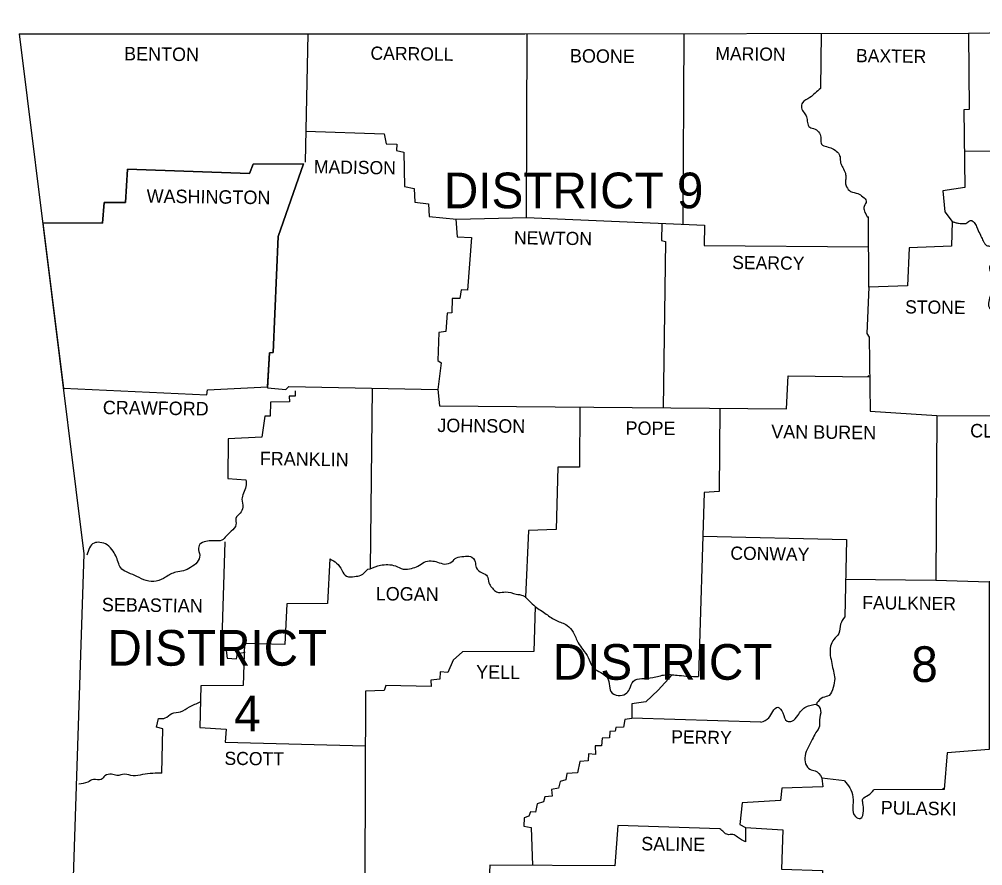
# Model space of a CAD drawing. Extents: x 31699 to 244310, y -8841 to 11474.
# Drawn here: x 77768 to 80783, y 7711 to 10358 of the extents above; entities that cross this region are included whole.
import ezdxf

# ---------------------------------------------------------------- set-up
doc = ezdxf.new("R2010")
doc.units = 0
for name, color, linetype in [('Level 48', 7, 'Continuous'), ('Level 60', 7, 'Continuous'), ('R_Border', 7, 'Continuous'), ('R_Border Prem', 7, 'Continuous'), ('R_Grid', 7, 'Continuous')]:
    doc.layers.add(name, color=color, linetype=linetype)

msp = doc.modelspace()

# ---------------------------------------------------------------- linework, layer by layer
at = {"layer": 'Level 48'}
for p, q in [((80421.5, 9740.6), (80425.4, 9740.6)), ((80263.9, 8220.2), (80263, 8215.3)), ((80279.6, 7986.3), (80279.6, 7984.4))]:
    msp.add_line(p, q, dxfattribs=at)
at = {"layer": 'Level 60'}
for p, q in [((77841.7, 9721.1), (77906.1, 9204.6)), ((78545, 9208.5), (78550.7, 9315))]:
    msp.add_line(p, q, dxfattribs=at)
for points in [[(78550.7, 9315), (78562.5, 9316), (78578.1, 9679), (78657.4, 9906), (78499.9, 9905), (78488.1, 9875.6), (78106.5, 9889.3), (78100.7, 9784.6), (78033.2, 9784.6), (78028.3, 9720.1), (77841.7, 9721.1)], [(77906.1, 9204.6), (78355.1, 9183.9), (78357, 9199.6), (78545, 9208.5)]]:
    msp.add_lwpolyline(points, dxfattribs=at)
at = {"layer": 'R_Border Prem'}
for p, q in [((78858.9, 8638.9), (78865.8, 8639.9)), ((79351.7, 8551.2), (79351.7, 8548.9)), ((78334.5, 8223.1), (78335, 8223.3))]:
    msp.add_line(p, q, dxfattribs=at)
for points in [[(77768, 10313), (79350.1, 10312), (80738.5, 10314.9), (82376.3, 10340.4), (83135.6, 10358)], [(77768, 10313), (77970.5, 8686.9), (77882.5, 6032.5)], [(78671.2, 10312.4), (78662.3, 9910.9)], [(78664.4, 10007.9), (78909.8, 9999.9), (78915.7, 9968.6), (78949, 9967.6), (78948, 9948), (78971.5, 9942.2), (78973.4, 9835.5), (79003.7, 9828.7), (79005.7, 9786.6), (79048.8, 9780.7), (79050.7, 9741.6), (79135.8, 9732.8), (79355, 9737.7), (79357, 10312)], [(79847.2, 10313.1), (79844.2, 9717.1)], [(80277.7, 10314), (80275.7, 10141.8)], [(80738.4, 10314.9), (80740.4, 10076.2), (80723.8, 10075.2), (80726.7, 9831.6), (80658.2, 9821.8), (80664.1, 9756.3), (80687.6, 9725.9), (80685.6, 9648.7), (80552.6, 9643.8), (80547.7, 9524.4), (80426.3, 9520.5), (80420.5, 9375.7), (80427.3, 9363.9), (80430.3, 9133), (80639.6, 9119.3), (80636.7, 8603.7), (80803, 8598.8), (80803, 8074.4), (80671.9, 8064.6), (80662.1, 7949.2), (80442, 7948.2)], [(81567.1, 10327.8), (81569.1, 10081.1), (81441.9, 10074.3), (81438, 9941.2), (80725.4, 9945.1)], [(77841.7, 9721.1), (78028.3, 9720.1), (78033.2, 9784.6), (78100.7, 9784.6), (78106.5, 9889.3), (78488.1, 9875.6), (78499.9, 9905), (78657.4, 9906), (78578.1, 9679), (78562.5, 9316), (78550.7, 9315), (78544.9, 9205.4), (78602.6, 9200.5), (78611.4, 9209.3), (79078.1, 9200.5), (79083, 9148.7)], [(80426.3, 9520.5), (80425.4, 9740.6)], [(79133.7, 9733), (79137.8, 9678), (79182.8, 9675.1), (79171.1, 9510.7), (79150.5, 9511.7), (79146.6, 9485.3), (79123.1, 9485.3), (79122.1, 9440.2), (79107.5, 9439.3), (79102.6, 9381.5), (79081, 9378.6), (79078.1, 9290.6), (79087.9, 9283.7), (79078.1, 9200.5)], [(79355, 9737.7), (79912.7, 9714.2), (79911.7, 9650.6), (80425.8, 9646.7)], [(79778.7, 9719.8), (79777.7, 9666.3), (79790.4, 9663.3), (79782.5, 9143)], [(79083, 9148.7), (80169, 9139.9), (80173.9, 9242.6), (80428.9, 9239.6)], [(80423.4, 9240.7), (80426.3, 9243.6)], [(77906.1, 9204.6), (78355.1, 9183.9), (78357, 9199.6), (78545, 9208.5)], [(78631, 9196.6), (78631, 9179), (78612.4, 9179), (78613.4, 9161.4), (78553.7, 9160.4), (78552.7, 9116.4), (78536.1, 9116.4), (78527.3, 9050.8), (78421.6, 9046), (78420.6, 8921.7), (78477.4, 8917.8)], [(78872.6, 9204.5), (78865.8, 8639.9)], [(79522.3, 9145.1), (79521.3, 8957.9), (79453.8, 8956.9), (79447.9, 8762.2), (79361.8, 8759.3), (79351.7, 8551.2)], [(79960.7, 9141.6), (79958.7, 8881.6), (79911.7, 8877.7), (79893.1, 8302.4)], [(80639.6, 9119.3), (81142.5, 9116.4), (81185.6, 9136.9), (81182.7, 8754.4), (81153.3, 8741.7), (81126.9, 8719.2), (81118.1, 8710.4), (81117.1, 8600.8), (80803, 8598.8)], [(78410.8, 8724.1), (78401, 8387.5), (78415.7, 8383.6), (78418.7, 8360.1), (78448, 8358.1), (78450.9, 8374.8), (78474.4, 8378.7)], [(79907.3, 8741.7), (80356.9, 8730.9), (80351, 8489.2)], [(78739.6, 8671.2), (78732.7, 8531.3), (78605.5, 8530.3), (78598.7, 8403.1), (78472.5, 8406.1), (78468.6, 8275), (78336.5, 8274), (78332.6, 8142.9), (78415.7, 8138), (78412.8, 8097.9), (78850.5, 8085.8)], [(80352, 8607.6), (80636.7, 8603.7)], [(79382.4, 8521.5), (79378.5, 8380.6), (79155.4, 8379.7), (79126, 8354.2), (79109.4, 8315.1), (79085, 8317), (79084, 8294.5), (79055.6, 8291.6), (79056.6, 8271.1), (78914.7, 8275), (78909.8, 8259.3), (78851.1, 8257.4), (78849.2, 7685)], [(79810.5, 8307.5), (79766.9, 8260.3), (79728.7, 8224.1), (79684.7, 8217.2), (79684.7, 8171.3), (79663.2, 8168.3), (79659.3, 8144.8), (79634.8, 8142.9), (79632.9, 8132.1), (79616.2, 8131.1), (79615.3, 8110.6), (79591.8, 8109.6), (79589.8, 8086.1), (79570.2, 8086.1), (79571.2, 8058.7), (79549.7, 8060.7), (79548.7, 8039.2), (79522.3, 8037.2), (79514.5, 8002), (79481.2, 7999.1), (79478.3, 7979.5), (79460.7, 7974.6), (79455.8, 7954), (79433.3, 7949.2), (79435.2, 7928.6), (79412.7, 7926.7), (79408.8, 7911), (79388.3, 7905.1), (79383.4, 7878.7), (79367.7, 7879.7), (79362.8, 7866), (79348.1, 7861.1), (79347.2, 7834.7), (79369.7, 7830.8), (79373.8, 7711.7)], [(78214.2, 8001), (78217.1, 8139), (78197.5, 8144.8), (78203.4, 8171.3)], [(80088.8, 8159.5), (79684.7, 8172.3)], [(80350, 7976.6), (80279.6, 7984.4), (80282.5, 7958), (80154.4, 7953.1), (80150.4, 7914.9), (80030.1, 7908.1), (80023.2, 7839.6), (80040.9, 7830.8), (80040.9, 7785.8)], [(80657.3, 7950.1), (80662.1, 7955)], [(79960.6, 7826.9), (79640.7, 7836.6), (79631.9, 7710.4), (79240.5, 7712.4), (79238.6, 7670.3)], [(80040.9, 7830.2), (80157.3, 7822.9), (80153.4, 7700.6), (80281.5, 7695.8), (80283.5, 7589.1), (80344.2, 7584.2), (80344.2, 7565.6), (80400.9, 7561.7), (80402.9, 7493.2), (80532, 7493.2), (80535.9, 7425.7), (80655.3, 7419.8), (80654.3, 7292.5)]]:
    msp.add_lwpolyline(points, dxfattribs=at)
for points in [[(80275.7, 10141.8), (80258.1, 10127.1), (80242.4, 10113.4), (80218.9, 10096.8), (80216, 10081.1), (80223.8, 10065.5), (80231.6, 10052.7), (80234.6, 10035.1), (80241.4, 10020.4), (80258.1, 10014.6), (80271.8, 10001.9), (80276.7, 9984.2), (80278.6, 9967.6), (80294.3, 9959.8), (80311.9, 9953.9), (80328.5, 9942.2), (80336.3, 9927.5), (80338.3, 9908.9), (80345.1, 9894.2), (80353, 9876.6), (80354.9, 9861.9), (80353, 9847.3), (80356.9, 9833.6), (80369.6, 9819.9), (80392.1, 9813), (80407.8, 9803.2), (80418.5, 9789.5), (80411.7, 9772.9), (80412.7, 9758.2), (80421.5, 9740.6)], [(80687.6, 9725.9), (80697.2, 9722.3), (80707, 9720.3), (80716.9, 9719.5), (80726.7, 9719.1), (80732.8, 9721.1), (80738.9, 9725.5), (80744.7, 9728.9), (80747.5, 9729.2), (80750.2, 9727.9), (80755.8, 9722.3), (80760.1, 9716), (80763.6, 9709.3), (80766.8, 9702.5), (80775.6, 9682.9), (80782.4, 9668.5), (80786.1, 9661.4), (80788.2, 9657.9), (80790.3, 9654.5), (80794.9, 9650.8), (80801.1, 9649.2), (80807.7, 9648), (80810.9, 9647.1), (80813.8, 9645.7), (80831.4, 9630.1), (80833.9, 9621.6), (80833.3, 9617.2), (80831.4, 9613.4), (80827.7, 9609.4), (80823.7, 9605.6), (80819.6, 9601.8), (80815.8, 9597.8), (80814, 9595.9), (80808.4, 9590.4), (80805.4, 9586.5), (80804.5, 9584.4), (80804, 9582.1), (80804.3, 9577.5), (80805.4, 9572.9), (80806.8, 9568.2), (80807.9, 9563.5), (80810, 9550.8), (80811.8, 9538.1), (80811.8, 9513.6), (80806, 9491.1), (80801.1, 9470.6), (80800.6, 9466.1), (80801.2, 9461.7), (80803, 9457.3), (80804.3, 9455.1), (80806, 9453), (80808, 9451.3), (80810.2, 9450.5), (80815.1, 9451.2), (80824.6, 9455.9), (80829.5, 9459.4), (80834.1, 9463.6), (80838.9, 9467.7), (80844.1, 9470.6), (80849.1, 9471.8), (80854.4, 9472.3), (80864.7, 9470.6), (80874.7, 9465.7), (80884.2, 9459.8), (80889.5, 9454.9), (80894.1, 9449), (80899, 9443.8), (80901.7, 9442.1), (80903.2, 9441.5), (80904.8, 9441.2), (80915, 9442.2), (80925.3, 9445.1), (80942, 9450), (80965.5, 9456.9), (80982.1, 9448.1), (80996.8, 9436.3), (81001.3, 9431.8), (81005.5, 9427), (81009.8, 9422.2), (81014.4, 9417.7), (81031, 9406), (81052.5, 9395.2), (81059, 9393.1), (81065.6, 9391.7), (81072.3, 9390.3), (81078.9, 9388.4), (81092.8, 9382.4), (81098.7, 9377.9), (81101.3, 9375.1), (81102.4, 9373.5), (81103.4, 9371.8), (81105, 9368.2), (81107.3, 9357.6), (81107.5, 9350.5), (81107.3, 9343.4), (81106.3, 9318.9), (81104.4, 9288.6), (81102.4, 9255.3), (81102, 9247.2), (81102.1, 9239.1), (81103, 9231), (81104, 9227), (81105.4, 9223), (81110.5, 9212), (81116.1, 9201.5), (81123.1, 9189), (81129.8, 9176.1), (81132.9, 9164.5), (81133.4, 9158.6), (81133.7, 9152.6), (81134.2, 9134.5), (81132.9, 9116.5)], [(78477.4, 8917.8), (78477.4, 8897.2), (78469.5, 8875.7), (78464.6, 8857.1), (78467.6, 8832.7), (78458.8, 8813.1), (78446.1, 8797.4), (78446.1, 8777.9), (78431.4, 8757.3), (78415.7, 8741.7), (78402, 8728.9), (78377.6, 8727), (78357, 8726), (78336.5, 8719.2), (78328.6, 8704.5), (78332.6, 8682), (78324.7, 8660.5), (78304.2, 8643.8), (78281.7, 8633.1), (78258.2, 8629.2), (78225.9, 8613.5), (78196.6, 8600.8), (78165.3, 8602.7), (78135.9, 8615.5), (78109.5, 8627.2), (78088.9, 8638.9), (78072.3, 8675.1), (78061.5, 8694.7), (78043, 8714.3), (78020.4, 8722.1), (78001.9, 8720.1), (77979.4, 8682)], [(78739.6, 8671.2), (78761.1, 8657.5), (78777.7, 8635), (78792.4, 8616.4), (78816.9, 8615.5), (78836.4, 8619.4), (78858.9, 8638.9)], [(78865.8, 8639.9), (78898.1, 8650.7), (78921.6, 8652.6), (78945, 8648.7), (78969.5, 8638.9), (78995.9, 8640.9), (79015.5, 8647.7), (79035.1, 8660.5), (79056.6, 8664.4), (79077.1, 8660.5), (79098.7, 8654.6), (79122.1, 8661.4), (79135.8, 8674.2), (79159.3, 8678.1), (79179.9, 8678.1), (79194.5, 8661.4), (79197.5, 8643.8), (79216.1, 8627.2), (79232.7, 8616.4), (79237.6, 8595.9), (79246.4, 8581.2), (79255.2, 8571.4), (79267.9, 8565.6), (79289.4, 8567.5), (79322.7, 8560.7), (79344.2, 8555.8), (79363.8, 8539.1), (79382.4, 8521.5)], [(79382.4, 8521.5), (79416.6, 8498), (79448.9, 8477.5), (79482.2, 8462.8), (79500.8, 8441.3), (79517.4, 8408), (79531.1, 8387.5), (79548.7, 8362), (79561.4, 8333.7), (79582, 8318), (79603.5, 8304.3), (79614.3, 8279.9), (79619.2, 8255.4), (79642.6, 8243.7), (79665.1, 8248.5), (79677.9, 8263.2), (79689.6, 8288.7), (79716, 8296.5), (79750.3, 8299.4), (79789.4, 8308.2), (79832.5, 8306.3), (79893.1, 8302.4)], [(80351, 8489.2), (80338.3, 8466.7), (80332.4, 8437.4), (80316.8, 8418.8), (80307, 8397.3), (80306, 8368.9), (80310.9, 8343.5), (80315.8, 8319), (80319.7, 8296.5), (80314.8, 8268.1), (80302.1, 8243.7), (80282.5, 8236.8), (80263.9, 8220.2)], [(78203.4, 8171.3), (78224.9, 8173.2), (78245.5, 8186.9), (78272.9, 8192.8), (78300.3, 8207.5), (78334.5, 8223.1)], [(80088.8, 8159.5), (80113.3, 8173.2), (80126, 8193.8), (80141.6, 8206.5), (80157.3, 8188.9), (80171, 8163.4), (80185.7, 8163.4), (80204.3, 8181), (80216, 8196.7), (80230.7, 8208.4), (80246.3, 8213.3), (80263, 8215.3), (80275.7, 8196.7), (80271.8, 8167.3), (80271.8, 8147.8), (80261, 8127.2), (80249.3, 8105.7), (80236.5, 8081.2), (80226.8, 8054.8), (80228.7, 8029.4), (80242.4, 8012.8), (80258.1, 8007.9), (80279.6, 7986.3)], [(78214.2, 8001), (78185.8, 8000), (78153.5, 7996.1), (78124.2, 7992.2), (78097.7, 7997.1), (78073.3, 7993.2), (78056.6, 7997.1), (78036.1, 7992.2), (78024.4, 7980.5), (77999.9, 7980.5), (77982.3, 7972.6), (77953.9, 7965.8)], [(80350, 7976.6), (80366.7, 7955), (80376.5, 7925.7), (80376.5, 7892.4), (80384.3, 7865), (80399.9, 7859.1), (80409.7, 7882.6), (80407.8, 7906.1), (80407.8, 7919.8), (80424.4, 7931.5), (80442, 7948.2)], [(80040.9, 7785.8), (80015.4, 7800.4), (80000.7, 7809.2), (79985.1, 7808.3), (79972.4, 7816.1), (79960.6, 7826.9)]]:
    msp.add_spline(points, degree=3, dxfattribs=at)

# ---------------------------------------------------------------- texts
at = {"layer": 'R_Border'}
for s, height, rotation, p in [('BENTON', 42.07, 359.2527, (78095.8, 10229.8)), ('CARROLL', 41.09, 359.1481, (78866.8, 10231.8)), ('BOONE', 42.07, 359.4001, (79491, 10223)), ('MARION', 41.09, 359.1854, (79946, 10230.8)), ('BAXTER', 41.09, 359.2559, (80386.2, 10224)), ('MADISON', 41.09, 359.0906, (78689.7, 9876.6)), ('WASHINGTON', 42.06, 359.232, (78166.2, 9784.6)), ('NEWTON', 41.09, 359.2717, (79315.9, 9654.5)), ('SEARCY', 41.08, 359.2527, (79998.8, 9577.2)), ('STONE', 41.08, 359.4001, (80539.8, 9438.3)), ('CRAWFORD', 42.06, 359.2771, (78029.3, 9123.2)), ('JOHNSON', 42.07, 359.3514, (79076.1, 9067.5)), ('POPE', 42.07, 359.6155, (79665.1, 9058.7)), ('VAN BUREN', 42.07, 359.3508, (80121.1, 9047.9)), ('CLEBURNE', 42.06, 359.2535, (80743.4, 9050.8)), ('FRANKLIN', 42.07, 359.1815, (78520.4, 8963.8)), ('CONWAY', 41.08, 359.0371, (79992.9, 8668.3)), ('LOGAN', 42.07, 359.3969, (78883.4, 8541.1)), ('SEBASTIAN', 42.06, 359.2816, (78026.3, 8506.8)), ('FAULKNER', 41.09, 359.2486, (80405.8, 8513.7)), ('YELL', 42.07, 359.1987, (79197.5, 8296.5)), ('PERRY', 41.09, 359.0858, (79808, 8094)), ('SCOTT', 41.09, 359.4063, (78409.9, 8026.5)), ('PULASKI', 42.07, 359.053, (80463.5, 7871.9)), ('SALINE', 42.07, 359.1491, (79714.1, 7759.3))]:
    msp.add_text(s, height=height, rotation=rotation, dxfattribs=at).set_placement(p)
at = {"layer": 'R_Grid'}
for s, height, p in [('DISTRICT 9', 111.54, (79096.7, 9767)), ('DISTRICT', 111.54, (78043.9, 8336.6)), ('DISTRICT', 111.54, (79437.2, 8292.6)), ('8', 111.5, (80559.4, 8285.7)), ('4', 111.5, (78440.2, 8131.1))]:
    msp.add_text(s, height=height, dxfattribs=at).set_placement(p)

doc.saveas('drawing.dxf')
